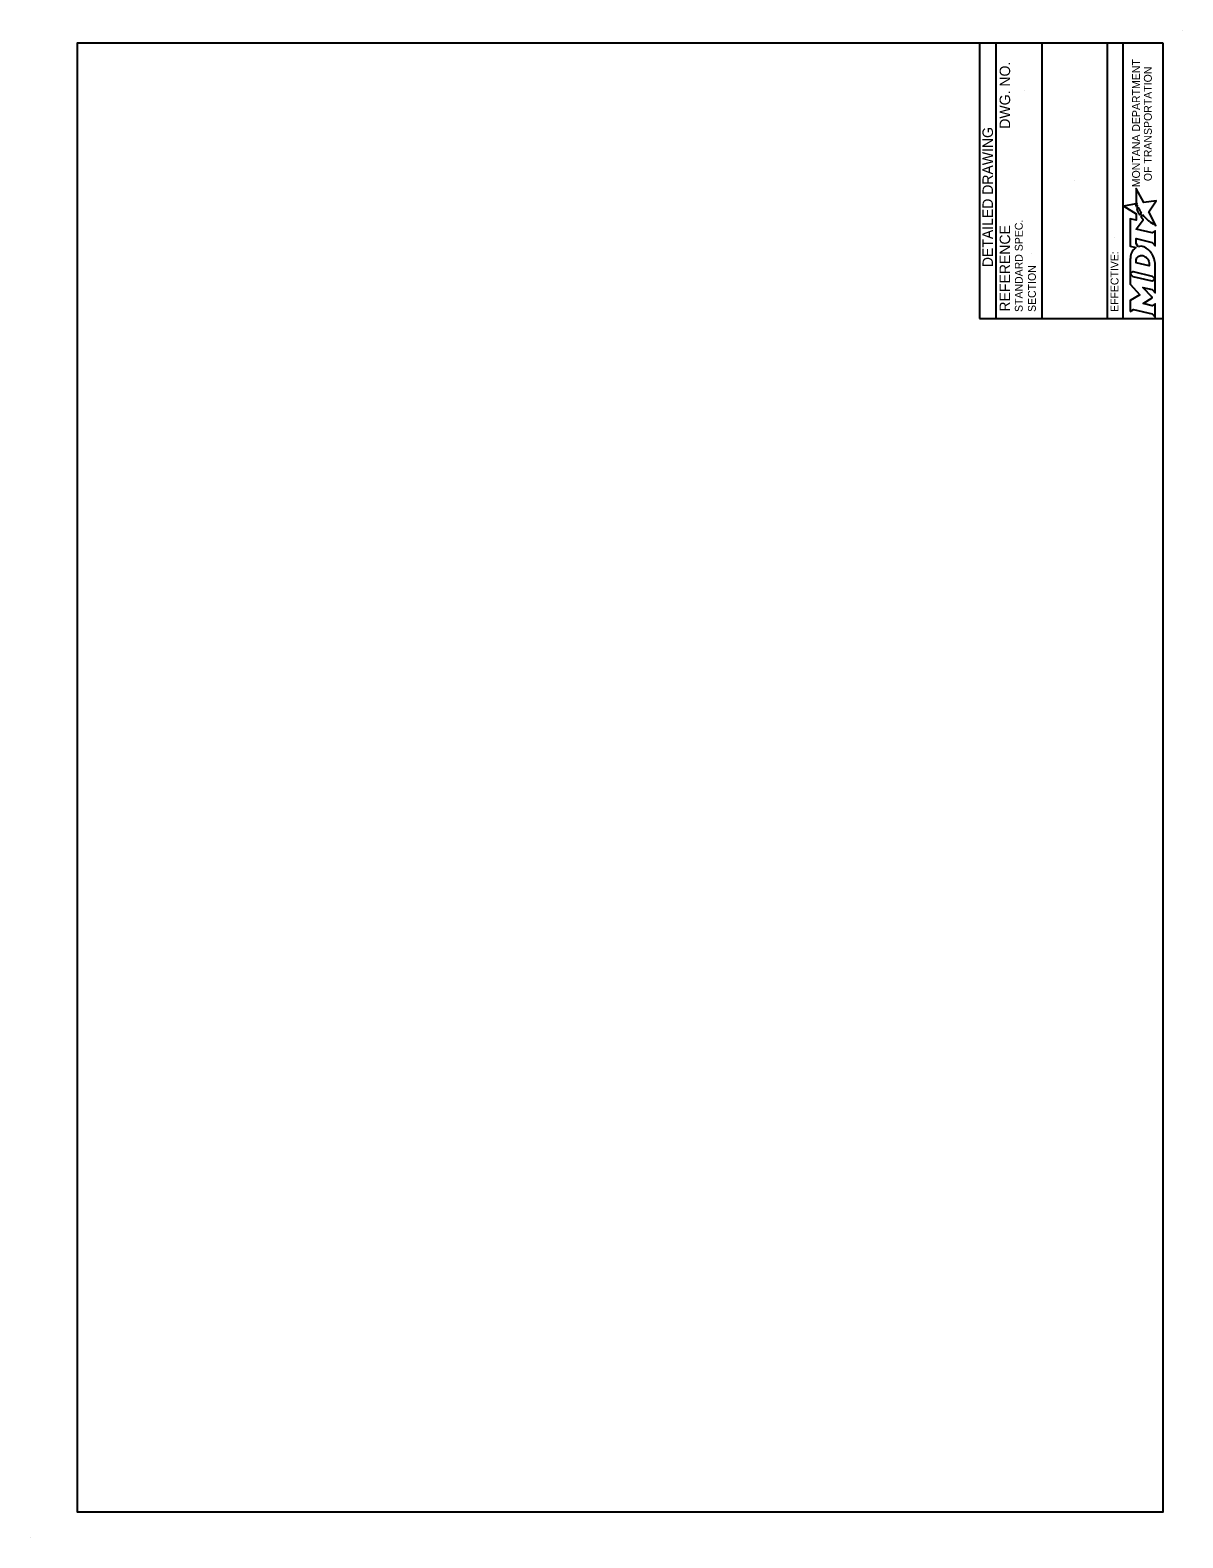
# Model space of a CAD drawing. Extents: x 49991.4 to 50021, y 49987.6 to 50011.4.
# Drawn here: x 49999.98 to 50008.76, y 49999.86 to 50011.36 of the extents above; entities that cross this region are included whole.
import ezdxf

# ---------------------------------------------------------------- set-up
doc = ezdxf.new("R2010")
doc.units = 0
doc.layers.add('Level 1', color=7, linetype='Continuous')
doc.layers.add('Level 3', color=7, linetype='Continuous')

msp = doc.modelspace()

# ---------------------------------------------------------------- linework, layer by layer
at = {"layer": 'Level 1'}
for p, q in [((50008.765, 50011.363), (50008.765, 50011.363)), ((49999.977, 49999.862), (49999.977, 49999.862))]:
    msp.add_line(p, q, dxfattribs=at)
msp.add_lwpolyline([(50008.615, 50011.263), (50000.336, 50011.263), (50000.336, 50000.062), (50008.615, 50000.062)], close=True, dxfattribs=at)
at = {"layer": 'Level 3'}
for p, q in [((50007.215, 50011.263), (50007.215, 50009.163)), ((50007.34, 50011.263), (50007.34, 50009.163)), ((50007.69, 50011.263), (50007.69, 50009.163)), ((50008.188, 50011.263), (50008.188, 50009.163)), ((50008.308, 50011.263), (50008.308, 50009.163)), ((50007.555, 50010.899), (50007.555, 50010.899)), ((50007.939, 50010.213), (50007.939, 50010.213)), ((50008.244, 50009.778), (50008.244, 50009.778)), ((50007.614, 50009.657), (50007.614, 50009.657)), ((50007.215, 50009.163), (50008.615, 50009.163))]:
    msp.add_line(p, q, dxfattribs=at)
for points in [[(50008.514, 50009.9), (50008.538, 50009.885), (50008.546, 50009.88), (50008.554, 50009.875), (50008.559, 50009.872), (50008.505, 50009.978), (50008.561, 50010.061), (50008.468, 50010.048), (50008.409, 50010.155), (50008.409, 50010.106), (50008.408, 50010.076), (50008.408, 50010.055), (50008.409, 50010.048), (50008.411, 50010.043), (50008.413, 50010.035), (50008.417, 50010.025)], [(50008.417, 50010.025), (50008.411, 50010.014), (50008.409, 50010.026), (50008.407, 50010.038), (50008.316, 50010.02), (50008.408, 50009.961), (50008.408, 50009.914), (50008.364, 50009.924), (50008.364, 50009.715), (50008.407, 50009.705), (50008.398, 50009.699)], [(50008.423, 50009.711), (50008.41, 50009.736), (50008.41, 50009.773), (50008.531, 50009.744), (50008.553, 50009.717), (50008.553, 50009.833), (50008.531, 50009.816), (50008.41, 50009.844), (50008.462, 50009.915), (50008.447, 50009.937), (50008.458, 50009.956)], [(50008.445, 50009.974), (50008.446, 50009.972), (50008.437, 50009.954), (50008.431, 50009.964), (50008.429, 50009.968), (50008.425, 50009.977), (50008.422, 50009.982), (50008.419, 50009.99), (50008.416, 50009.998), (50008.424, 50010.009), (50008.426, 50010.005), (50008.428, 50010.001), (50008.431, 50009.997), (50008.434, 50009.992), (50008.435, 50009.99), (50008.436, 50009.987), (50008.438, 50009.985), (50008.439, 50009.982), (50008.441, 50009.98), (50008.443, 50009.977), (50008.445, 50009.974)], [(50008.498, 50009.914), (50008.498, 50009.914)], [(50008.364, 50009.62), (50008.364, 50009.506), (50008.387, 50009.521), (50008.531, 50009.487), (50008.553, 50009.462), (50008.553, 50009.572)], [(50008.451, 50009.644), (50008.459, 50009.643), (50008.468, 50009.64), (50008.476, 50009.635), (50008.484, 50009.63), (50008.491, 50009.623), (50008.497, 50009.615), (50008.502, 50009.607), (50008.506, 50009.598), (50008.508, 50009.589), (50008.509, 50009.58), (50008.509, 50009.564), (50008.409, 50009.587), (50008.409, 50009.603), (50008.41, 50009.611), (50008.412, 50009.619), (50008.415, 50009.625), (50008.419, 50009.631), (50008.424, 50009.636), (50008.43, 50009.64), (50008.436, 50009.642), (50008.443, 50009.644), (50008.446, 50009.644), (50008.451, 50009.644)], [(50008.546, 50009.618), (50008.543, 50009.626), (50008.538, 50009.639), (50008.527, 50009.66)], [(50008.387, 50009.481), (50008.364, 50009.506), (50008.364, 50009.424), (50008.437, 50009.344), (50008.364, 50009.3), (50008.364, 50009.218)], [(50008.364, 50009.218), (50008.388, 50009.232), (50008.531, 50009.198), (50008.553, 50009.173), (50008.553, 50009.274), (50008.531, 50009.261), (50008.461, 50009.277), (50008.53, 50009.321), (50008.53, 50009.326), (50008.46, 50009.401), (50008.531, 50009.385), (50008.553, 50009.36), (50008.553, 50009.462), (50008.53, 50009.448), (50008.387, 50009.481)]]:
    msp.add_lwpolyline(points, dxfattribs=at)
for centre, radius, start, end in [((50008.443, 50009.643), 0.0709, 69.5329, 105.8582), ((50008.425, 50009.599), 0.118, 30.9103, 69.1383)]:
    msp.add_arc(centre, radius, start, end, dxfattribs=at)
for centre, major_axis, ratio, start_param, end_param in [((50008.468, 50009.945), (0.0097, -0.0112), 0.021651, 3.157348, 6.283185), ((50008.487, 50009.924), (0.0102, -0.0098), 0.016458, 3.141593, 6.279097), ((50008.506, 50009.907), (0.00806, -0.00694), 0.008222, 0, 3.137361), ((50008.412, 50009.618), (0.0037, 0.0834), 0.568097, 0.61298, 1.570796), ((50008.404, 50009.673), (0.0295, 0.0361), 0.469099, 1.225588, 1.570796), ((50008.405, 50009.573), (-0.148, 0), 0.987302, 3.139398, 3.456847)]:
    msp.add_ellipse(centre, major_axis=major_axis, ratio=ratio, start_param=start_param, end_param=end_param, dxfattribs=at)

# ---------------------------------------------------------------- texts
for s, height, p in [('DWG. NO.', 0.08, (50007.448, 50010.611)), ('MONTANA DEPARTMENT', 0.06, (50008.438, 50010.165)), ('OF TRANSPORTATION', 0.06, (50008.528, 50010.211)), ('DETAILED DRAWING', 0.0799, (50007.317, 50009.555)), ('REFERENCE', 0.08, (50007.448, 50009.216)), ('STANDARD SPEC.', 0.06, (50007.544, 50009.213)), ('EFFECTIVE:', 0.06, (50008.274, 50009.213)), ('SECTION', 0.06, (50007.644, 50009.213))]:
    msp.add_text(s, height=height, rotation=90, dxfattribs=at).set_placement(p)

doc.saveas('drawing.dxf')
